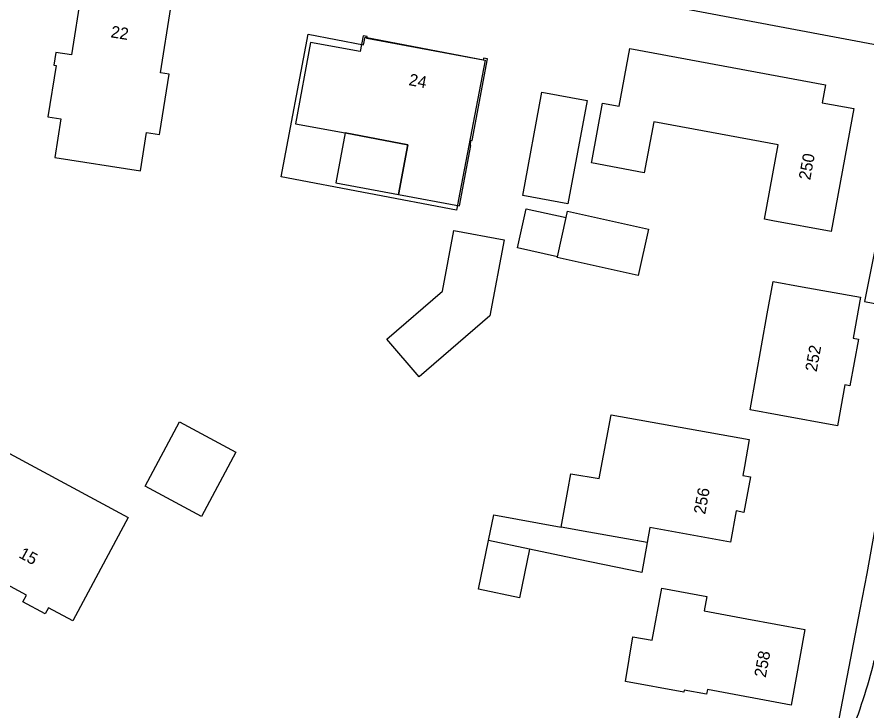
# Model space of a CAD drawing. Extents: x 161258 to 161838, y 380836 to 381727.
# Drawn here: x 161655.9 to 161727.6, y 381087.2 to 381145.7 of the extents above; entities that cross this region are included whole.
import ezdxf

# ---------------------------------------------------------------- set-up
doc = ezdxf.new("R2010")
doc.units = 0
for name, color, linetype in [('IMGEO_Fietspad_open', 7, 'Continuous'), ('IMGEO_Pand', 7, 'Continuous'), ('IMGEO_Pand_nummerreeks', 7, 'Continuous'), ('IMGEO_Pand_overbouw', 7, 'Continuous'), ('IMGEO_Pand_vergunning_verleend', 7, 'Continuous'), ('IMGEO_Voetpad_open', 7, 'Continuous')]:
    doc.layers.add(name, color=color, linetype=linetype)

msp = doc.modelspace()

# ---------------------------------------------------------------- linework, layer by layer
at = {"layer": 'IMGEO_Fietspad_open'}
msp.add_arc((161680.587, 381103.32), 49.109, 338.05681, 345.99538, dxfattribs=at)
at = {"layer": 'IMGEO_Pand'}
for points in [[(161668.026, 381141.014), (161668.9, 381146.511), (161661.358, 381147.71), (161660.533, 381142.516), (161659.21, 381142.727), (161659.038, 381141.641), (161659.236, 381141.61), (161658.549, 381137.285), (161659.644, 381137.111), (161659.13, 381133.874), (161666.344, 381132.729), (161666.858, 381135.966), (161667.964, 381135.79), (161667.991, 381135.958), (161668.776, 381140.895), (161668.026, 381141.014)], [(161695.61, 381142.176), (161695.288, 381142.238), (161695.256, 381142.074), (161685.427, 381143.903), (161685.456, 381144.064), (161685.137, 381144.124), (161684.887, 381142.795), (161680.699, 381143.566), (161679.41, 381136.715), (161683.6, 381135.93), (161688.892, 381134.939), (161688.106, 381130.743), (161693.246, 381129.779), (161694.198, 381134.861), (161694.139, 381134.872), (161694.224, 381135.324), (161694.322, 381135.306), (161695.61, 381142.176)], [(161704.393, 381133.4), (161704.415, 381133.519), (161705.324, 381138.435), (161706.721, 381138.177), (161707.621, 381143.045), (161724.122, 381139.996), (161723.841, 381138.472), (161726.511, 381137.982), (161724.596, 381127.62), (161719.68, 381128.529), (161718.982, 381128.658), (161720.14, 381134.922), (161709.629, 381136.865), (161708.837, 381132.578), (161704.393, 381133.4)], [(161700.192, 381139.383), (161704.007, 381138.679), (161702.397, 381129.957), (161698.582, 381130.661), (161700.192, 381139.383)], [(161701.505, 381125.499), (161698.157, 381126.244), (161698.889, 381129.539), (161702.238, 381128.794)], [(161702.238, 381128.794), (161702.359, 381129.34), (161709.197, 381127.819), (161708.328, 381123.914), (161701.489, 381125.425), (161701.505, 381125.499)], [(161701.505, 381125.499), (161702.238, 381128.794)], [(161692.767, 381127.7), (161697.007, 381126.922), (161695.812, 381120.499), (161689.848, 381115.366), (161687.122, 381118.535), (161691.829, 381122.585), (161692.767, 381127.7)], [(161719.699, 381123.398), (161722.15, 381122.957), (161727.07, 381122.071), (161726.451, 381118.627), (161726.894, 381118.548), (161726.175, 381114.603), (161725.741, 381114.68), (161725.123, 381111.249), (161720.203, 381112.134), (161717.754, 381112.575), (161718.239, 381115.271), (161719.213, 381120.692), (161719.699, 381123.398)], [(161701.83, 381102.697), (161702.39, 381105.793), (161702.641, 381107.182), (161705.043, 381106.804), (161706.032, 381112.164), (161717.681, 381110.076), (161717.275, 381107.812), (161717.139, 381107.055), (161717.785, 381106.938), (161717.243, 381103.936), (161716.587, 381104.055), (161716.115, 381101.437), (161709.306, 381102.667), (161709.075, 381101.388)], [(161669.642, 381111.575), (161674.398, 381109.018), (161671.494, 381103.596), (161666.738, 381106.154), (161669.642, 381111.575)], [(161665.322, 381103.509), (161663.01, 381099.191), (161660.649, 381094.783), (161658.583, 381095.89), (161658.309, 381095.378), (161656.425, 381096.386), (161656.736, 381096.967), (161650.259, 381100.435), (161651.075, 381101.959), (161650.701, 381102.159), (161651.21, 381103.11), (161651.598, 381102.902), (161654.932, 381109.096), (161665.322, 381103.509)], [(161695.703, 381101.556), (161696.155, 381103.722), (161701.83, 381102.697)], [(161709.075, 381101.388), (161704.155, 381102.277), (161701.83, 381102.697)], [(161699.169, 381100.833), (161698.315, 381096.737), (161694.849, 381097.46), (161695.703, 381101.556)], [(161699.169, 381100.833), (161695.703, 381101.556)], [(161709.075, 381101.388), (161708.619, 381098.865), (161703.302, 381099.971), (161699.169, 381100.833)], [(161714.099, 381096.852), (161713.873, 381095.624), (161717.472, 381094.961), (161722.389, 381094.054), (161721.212, 381087.667), (161714.161, 381089.006), (161714.086, 381088.596), (161712.197, 381088.938), (161712.165, 381088.763), (161707.248, 381089.668), (161707.882, 381093.455), (161709.503, 381093.156), (161710.313, 381097.55), (161714.099, 381096.852)]]:
    msp.add_lwpolyline(points, dxfattribs=at)
at = {"layer": 'IMGEO_Pand_overbouw'}
msp.add_lwpolyline([(161688.106, 381130.743), (161688.892, 381134.939), (161683.6, 381135.93), (161682.814, 381131.736)], close=True, dxfattribs=at)
at = {"layer": 'IMGEO_Pand_vergunning_verleend'}
msp.add_lwpolyline([(161678.207, 381132.236), (161680.497, 381144.263), (161685.166, 381143.374), (161685.286, 381144.007), (161695.413, 381142.073), (161693.282, 381130.914), (161692.998, 381129.421), (161678.207, 381132.236)], dxfattribs=at)
at = {"layer": 'IMGEO_Voetpad_open'}
for points in [[(161705.296, 381147.752), (161729.059, 381143.246)], [(161730.949, 381139.425), (161727.413, 381121.716), (161731.644, 381120.893), (161729.527, 381109.474), (161727.597, 381098.784), (161727.016, 381095.753), (161724.997, 381085.219), (161720.455, 381086.078), (161717.949, 381073.189), (161718.093, 381073.156), (161712.712, 381055.485)]]:
    msp.add_lwpolyline(points, dxfattribs=at)

# ---------------------------------------------------------------- texts
at = {"layer": 'IMGEO_Pand_nummerreeks'}
for s, rotation, p in [('22', 350.96446, (161663.795, 381144.001)), ('24', 349.18829, (161688.923, 381139.972)), ('250', 79.52931, (161722.826, 381131.907)), ('252', 79.80156, (161723.371, 381115.746)), ('256', 79.68724, (161713.969, 381103.72)), ('15', 331.45449, (161656.012, 381100.173)), ('258', 79.56092, (161719.073, 381089.964))]:
    msp.add_text(s, height=1, rotation=rotation, dxfattribs=at).set_placement(p)

doc.saveas('drawing.dxf')
